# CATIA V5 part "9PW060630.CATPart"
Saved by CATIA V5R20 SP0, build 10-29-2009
Part number: 9PW060630
Revision: ANY
Definition: UNKNOWN
Nomenclature: 9PW060630
Source: Unknown
Bounding box of the stored display mesh (mm): x -174.5 to 0, y -11.046 to 3, z -3.1 to 3.1
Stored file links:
  C:\Users\Utente\Desktop\IO LAVORO\3D X SITO CF\CUMSA\3D files PW\pw060630\pw060630_ejection\9PW060630.CATPart
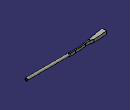
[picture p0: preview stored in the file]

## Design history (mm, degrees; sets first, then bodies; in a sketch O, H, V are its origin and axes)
Body1 "Chaflán2" (main body)
  Solid1: solid without history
